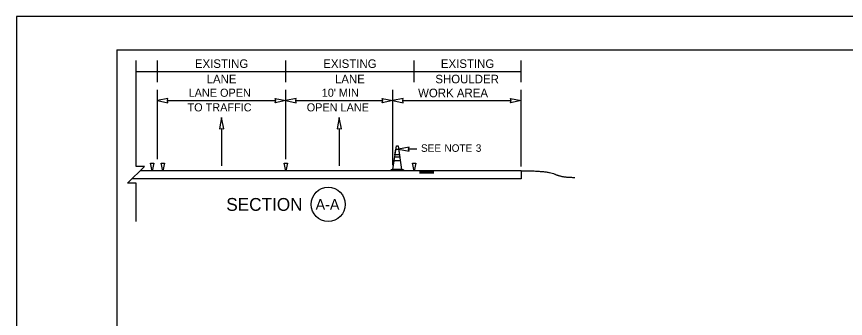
# Model space of a CAD drawing. Extents: x 99999.1 to 100096.1, y 99995 to 100010.7.
# Drawn here: x 100019.06 to 100026.81, y 100007.86 to 100010.69 of the extents above; entities that cross this region are included whole.
import ezdxf

# ---------------------------------------------------------------- set-up
doc = ezdxf.new("R2010")
doc.units = 0
for name, color, linetype in [('SH_GI_PlotLimits', 7, 'Continuous'), ('SH_GI_SheetBorder', 7, 'Continuous'), ('SH_TI_WZSectionCut', 7, 'Continuous'), ('TR_WZ_ArrowLeftStrRightTurn', 7, 'Continuous'), ('TR_WZ_TrafficConeElev', 7, 'Continuous'), ('TR_WZ_WorkZoneDetails', 7, 'Continuous'), ('TR_WZ_WorkZoneTextCurrent', 7, 'Continuous')]:
    doc.layers.add(name, color=color, linetype=linetype)

msp = doc.modelspace()

# ---------------------------------------------------------------- linework, layer by layer
at = {"layer": 'SH_GI_PlotLimits'}
msp.add_lwpolyline([(100019.0625, 99999.6875), (100036.0625, 99999.6875), (100036.0625, 100010.6875), (100019.0625, 100010.6875)], close=True, dxfattribs=at)
at = {"layer": 'SH_GI_SheetBorder'}
for q in [(100020, 100000), (100035.75, 100010.375)]:
    msp.add_line((100020, 100010.375), q, dxfattribs=at)
at = {"layer": 'SH_TI_WZSectionCut'}
for p, q in [((100020.38, 100010.075), (100020.38, 100010.275)), ((100021.58, 100010.075), (100021.58, 100010.275)), ((100022.78, 100010.075), (100022.78, 100010.275)), ((100023.78, 100010.075), (100023.78, 100010.275)), ((100020.18, 100010.175), (100020.38, 100010.175)), ((100020.38, 100010.175), (100021.58, 100010.175)), ((100021.58, 100010.175), (100022.78, 100010.175)), ((100022.78, 100010.175), (100023.78, 100010.175)), ((100020.38, 100009.3547), (100020.38, 100010.001)), ((100021.58, 100009.3547), (100021.58, 100010.001)), ((100022.58, 100009.2975), (100022.58, 100010.001)), ((100023.78, 100009.2849), (100023.78, 100010.001)), ((100020.4738, 100009.901), (100021.4863, 100009.901)), ((100021.6738, 100009.901), (100022.4863, 100009.901)), ((100022.6738, 100009.901), (100023.6863, 100009.901)), ((100023.78, 100009.2449), (100020.2188, 100009.2449)), ((100022.963, 100009.2393), (100022.83, 100009.2393)), ((100022.963, 100009.2337), (100022.83, 100009.2337)), ((100022.963, 100009.228), (100022.83, 100009.228)), ((100022.963, 100009.2228), (100022.83, 100009.2228)), ((100023.78, 100009.2449), (100023.78, 100009.1699)), ((100023.78, 100009.1699), (100020.1413, 100009.1699))]:
    msp.add_line(p, q, dxfattribs=at)
for points in [[(100020.38, 100009.901), (100020.4783, 100009.8817), (100020.4738, 100009.901), (100020.4783, 100009.9203)], [(100021.58, 100009.901), (100021.4817, 100009.8817), (100021.4863, 100009.901), (100021.4817, 100009.9203)], [(100021.58, 100009.901), (100021.6783, 100009.8817), (100021.6738, 100009.901), (100021.6783, 100009.9203)], [(100022.58, 100009.901), (100022.4817, 100009.8817), (100022.4863, 100009.901), (100022.4817, 100009.9203)], [(100022.58, 100009.901), (100022.6783, 100009.8817), (100022.6738, 100009.901), (100022.6783, 100009.9203)], [(100023.78, 100009.901), (100023.6817, 100009.8817), (100023.6863, 100009.901), (100023.6817, 100009.9203)], [(100020.3133, 100009.3147), (100020.3467, 100009.3147), (100020.33, 100009.2449)], [(100020.4133, 100009.3147), (100020.4467, 100009.3147), (100020.43, 100009.2449)], [(100021.5634, 100009.3147), (100021.5967, 100009.3147), (100021.5801, 100009.2449)], [(100022.7634, 100009.3147), (100022.7967, 100009.3147), (100022.7801, 100009.2449)]]:
    msp.add_lwpolyline(points, close=True, dxfattribs=at)
msp.add_circle((100021.9766, 100008.93), 0.16, dxfattribs=at)
msp.add_open_spline([(100023.78, 100009.2449), (100024.0312, 100009.2451), (100024.1567, 100009.183), (100024.2822, 100009.1831)], degree=2, dxfattribs=at)
at = {"layer": 'TR_WZ_ArrowLeftStrRightTurn'}
for p, q in [((100020.98, 100009.6418), (100020.98, 100009.292)), ((100022.08, 100009.6418), (100022.08, 100009.292))]:
    msp.add_line(p, q, dxfattribs=at)
for points in [[(100020.98, 100009.742), (100020.9594, 100009.6369), (100020.98, 100009.6418), (100021.0006, 100009.6369)], [(100022.08, 100009.742), (100022.0594, 100009.6369), (100022.08, 100009.6418), (100022.1006, 100009.6369)]]:
    msp.add_lwpolyline(points, close=True, dxfattribs=at)
at = {"layer": 'TR_WZ_TrafficConeElev'}
for p, q in [((100022.6008, 100009.3929), (100022.6091, 100009.4471)), ((100022.6091, 100009.4471), (100022.6343, 100009.4471)), ((100022.6343, 100009.4471), (100022.6426, 100009.3929)), ((100022.5925, 100009.3388), (100022.5982, 100009.3763)), ((100022.6509, 100009.3388), (100022.5925, 100009.3388)), ((100022.5982, 100009.3763), (100022.6452, 100009.3763)), ((100022.6426, 100009.3929), (100022.6008, 100009.3929)), ((100022.6452, 100009.3763), (100022.6509, 100009.3388)), ((100022.5639, 100009.2533), (100022.5681, 100009.2575)), ((100022.5639, 100009.245), (100022.5639, 100009.2533)), ((100022.6634, 100009.2575), (100022.6753, 100009.2575)), ((100022.6753, 100009.2575), (100022.6795, 100009.2533)), ((100022.6795, 100009.2533), (100022.6795, 100009.245)), ((100022.6795, 100009.245), (100022.5639, 100009.245))]:
    msp.add_line(p, q, dxfattribs=at)
msp.add_lwpolyline([(100022.6634, 100009.2575), (100022.58, 100009.2575), (100022.6139, 100009.4783), (100022.6295, 100009.4783)], close=True, dxfattribs=at)
msp.add_lwpolyline([(100022.6634, 100009.2575), (100022.58, 100009.2575), (100022.6139, 100009.4783), (100022.6295, 100009.4783)], close=True, dxfattribs=at)
msp.add_lwpolyline([(100022.5681, 100009.2575), (100022.58, 100009.2575), (100022.6634, 100009.2575)], dxfattribs=at)
at = {"layer": 'TR_WZ_WorkZoneDetails'}
msp.add_line((100022.8043, 100009.4471), (100022.7281, 100009.4471), dxfattribs=at)
msp.add_lwpolyline([(100020.18, 100008.7701), (100020.18, 100009.13), (100020.1, 100009.13), (100020.2601, 100009.2849), (100020.18, 100009.2849), (100020.18, 100010.275)], dxfattribs=at)
msp.add_lwpolyline([(100022.6343, 100009.4471), (100022.7326, 100009.4279), (100022.728, 100009.4472), (100022.7326, 100009.4664)], close=True, dxfattribs=at)

# ---------------------------------------------------------------- texts
at = {"layer": 'SH_TI_WZSectionCut'}
for s, height, p in [('EXISTING', 0.08, (100020.7302, 100010.207)), ('EXISTING', 0.08, (100021.9302, 100010.207)), ('EXISTING', 0.08, (100023.0302, 100010.207)), ('LANE', 0.08, (100020.8396, 100010.063)), ('LANE', 0.08, (100022.0396, 100010.063)), ('SHOULDER', 0.08, (100022.9783, 100010.063)), ('SECTION', 0.12, (100021.0235, 100008.87)), ('A-A', 0.1, (100021.8587, 100008.88))]:
    msp.add_text(s, height=height, rotation=360, dxfattribs=at).set_placement(p)
for s, height, p in [('LANE OPEN', 0.076, (100020.6714, 100009.937)), ("10' MIN", 0.076, (100021.9161, 100009.937)), ('WORK AREA', 0.08, (100022.8171, 100009.933)), ('TO TRAFFIC', 0.076, (100020.6613, 100009.8002)), ('OPEN LANE', 0.076, (100021.7758, 100009.8002))]:
    msp.add_text(s, height=height, dxfattribs=at).set_placement(p)
at = {"layer": 'TR_WZ_WorkZoneTextCurrent'}
for s, p in [('SEE', (100022.8443, 100009.4221)), ('NOTE', (100023.0635, 100009.4221)), ('3', (100023.3567, 100009.4221))]:
    msp.add_text(s, height=0.07, dxfattribs=at).set_placement(p)

doc.saveas('drawing.dxf')
